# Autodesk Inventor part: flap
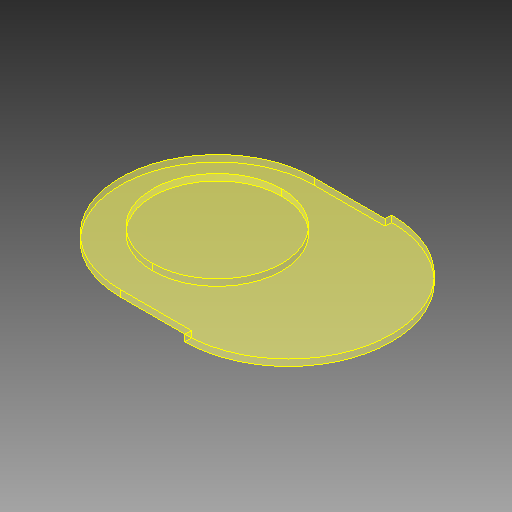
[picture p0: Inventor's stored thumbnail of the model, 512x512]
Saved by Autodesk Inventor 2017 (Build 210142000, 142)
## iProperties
Created: 2020-03
Part Number: flap
Material: Generic
Document SubType Name: Modeling
Designer: user
Density: 1 g/cm^3
Appearance: Default
Author: user
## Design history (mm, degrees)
feature "Composite1"
body "Srf1"
